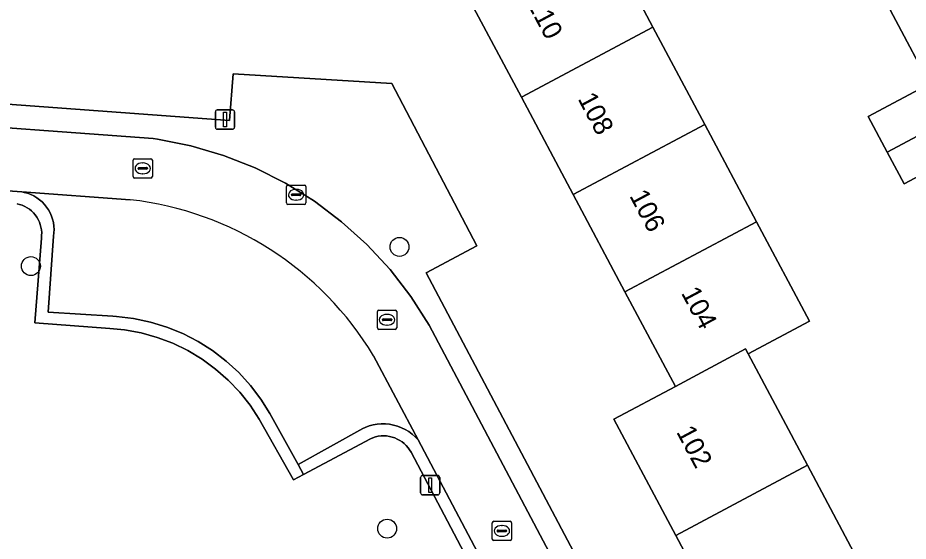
# Model space of a CAD drawing. Extents: x 160304 to 160955, y 383684 to 384161.
# Drawn here: x 160553.59 to 160599.67, y 383895.48 to 383922.54 of the extents above; entities that cross this region are included whole.
import ezdxf

# ---------------------------------------------------------------- set-up
doc = ezdxf.new("R2010")
doc.units = 0
for name, color, linetype in [('IMGEO_Boom', 7, 'Continuous'), ('IMGEO_Erf', 7, 'Continuous'), ('IMGEO_Groenvoorziening', 7, 'Continuous'), ('IMGEO_Kolk', 7, 'Continuous'), ('IMGEO_Lichtmast', 7, 'Continuous'), ('IMGEO_Pand', 7, 'Continuous'), ('IMGEO_Pand_nummerreeks', 7, 'Continuous'), ('IMGEO_Parkeervlak_open', 7, 'Continuous'), ('IMGEO_Rijbaan_lokaal_open', 7, 'Continuous'), ('IMGEO_Rioolput', 7, 'Continuous'), ('IMGEO_Voetpad_open', 7, 'Continuous')]:
    doc.layers.add(name, color=color, linetype=linetype)

msp = doc.modelspace()

# ---------------------------------------------------------------- linework, layer by layer
at = {"layer": 'IMGEO_Boom'}
for centre in [(160573.341, 383910.695), (160554.265, 383909.703), (160572.704, 383896.124)]:
    msp.add_circle(centre, 0.489, dxfattribs=at)
at = {"layer": 'IMGEO_Erf'}
for points in [[(160583.724, 383927.208), (160586.463, 383922.067), (160589.145, 383917.032), (160591.827, 383911.997), (160594.565, 383906.858), (160591.388, 383905.166), (160594.458, 383899.403), (160597.603, 383893.497), (160599.049, 383890.783), (160599.714, 383890.581)], [(160602.636, 383915.645), (160599.458, 383913.953), (160598.584, 383915.595), (160597.607, 383917.431), (160600.784, 383919.123), (160597.283, 383925.699)], [(160519.759, 383920.534), (160564.54, 383917.241), (160564.726, 383919.653), (160572.939, 383919.144), (160577.354, 383910.75), (160574.721, 383909.349), (160588.559, 383883.201), (160593.071, 383885.591), (160590.792, 383889.87), (160587.646, 383895.777), (160584.445, 383901.786), (160587.621, 383903.478), (160585.015, 383908.37), (160582.333, 383913.405), (160579.651, 383918.439), (160576.913, 383923.58)]]:
    msp.add_lwpolyline(points, dxfattribs=at)
at = {"layer": 'IMGEO_Groenvoorziening'}
msp.add_lwpolyline([(160576.867, 383894.551), (160573.94, 383900.071), (160573.867, 383900.195), (160573.783, 383900.312), (160573.689, 383900.42), (160573.585, 383900.52), (160573.473, 383900.611), (160573.354, 383900.691), (160573.227, 383900.759), (160573.095, 383900.817), (160572.959, 383900.862), (160572.819, 383900.895), (160572.677, 383900.916), (160572.533, 383900.923), (160572.389, 383900.918), (160572.247, 383900.9), (160572.106, 383900.869), (160571.969, 383900.826), (160571.848, 383900.776), (160568.374, 383898.921), (160567.854, 383898.643), (160566.087, 383901.784), (160565.611, 383902.506), (160565.073, 383903.183), (160564.476, 383903.809), (160563.826, 383904.379), (160563.127, 383904.888), (160562.386, 383905.333), (160561.607, 383905.711), (160560.799, 383906.017), (160559.966, 383906.249), (160559.115, 383906.407), (160558.358, 383906.482), (160554.474, 383906.761), (160554.807, 383911.153), (160554.821, 383911.293), (160554.822, 383911.434), (160554.81, 383911.575), (160554.786, 383911.714), (160554.749, 383911.85), (160554.701, 383911.983), (160554.641, 383912.11), (160554.569, 383912.232), (160554.488, 383912.347), (160554.396, 383912.454), (160554.295, 383912.553), (160554.185, 383912.642), (160554.068, 383912.721), (160553.945, 383912.789), (160553.816, 383912.846), (160553.682, 383912.891), (160553.545, 383912.924)], dxfattribs=at)
at = {"layer": 'IMGEO_Kolk'}
for p, q in [((160559.553, 383914.332), (160559.553, 383915.184)), ((160559.628, 383915.258), (160560.48, 383915.258)), ((160560.041, 383915.038), (160560.066, 383915.038)), ((160560.554, 383915.184), (160560.554, 383914.332)), ((160559.812, 383914.752), (160559.812, 383914.764)), ((160560.25, 383914.715), (160559.852, 383914.715)), ((160559.855, 383914.801), (160560.253, 383914.801)), ((160560.296, 383914.764), (160560.296, 383914.752)), ((160560.48, 383914.258), (160559.628, 383914.258)), ((160560.064, 383914.478), (160560.039, 383914.478)), ((160572.197, 383906.502), (160572.197, 383907.354)), ((160572.272, 383907.428), (160573.124, 383907.428)), ((160572.685, 383907.208), (160572.71, 383907.208)), ((160573.198, 383907.354), (160573.198, 383906.502)), ((160572.456, 383906.922), (160572.456, 383906.934)), ((160572.894, 383906.885), (160572.496, 383906.885)), ((160572.499, 383906.971), (160572.897, 383906.971)), ((160572.94, 383906.934), (160572.94, 383906.922)), ((160573.124, 383906.428), (160572.272, 383906.428)), ((160572.708, 383906.648), (160572.683, 383906.648)), ((160578.143, 383895.58), (160578.143, 383896.432)), ((160578.218, 383896.506), (160579.07, 383896.506)), ((160578.631, 383896.286), (160578.656, 383896.286)), ((160579.144, 383896.432), (160579.144, 383895.58)), ((160578.402, 383896), (160578.402, 383896.012)), ((160578.84, 383895.963), (160578.442, 383895.963)), ((160578.445, 383896.049), (160578.843, 383896.049)), ((160578.654, 383895.726), (160578.629, 383895.726)), ((160578.886, 383896.012), (160578.886, 383896)), ((160579.07, 383895.506), (160578.218, 383895.506))]:
    msp.add_line(p, q, dxfattribs=at)
for points in [[(160559.553, 383914.332), (160559.553, 383915.184)], [(160559.628, 383915.258), (160560.48, 383915.258)], [(160560.554, 383915.184), (160560.554, 383914.332)], [(160560.48, 383914.258), (160559.628, 383914.258)], [(160572.197, 383906.502), (160572.197, 383907.354)], [(160572.272, 383907.428), (160573.124, 383907.428)], [(160573.198, 383907.354), (160573.198, 383906.502)], [(160573.124, 383906.428), (160572.272, 383906.428)], [(160578.143, 383895.58), (160578.143, 383896.432)], [(160578.218, 383896.506), (160579.07, 383896.506)], [(160579.144, 383896.432), (160579.144, 383895.58)], [(160579.07, 383895.506), (160578.218, 383895.506)]]:
    msp.add_lwpolyline(points, dxfattribs=at)
for centre, radius, start, end in [((160559.63, 383915.182), 0.0765, 91.552, 178.448), ((160559.63, 383915.182), 0.0765, 91.552, 178.448), ((160560.478, 383915.182), 0.0765, 1.552, 88.448), ((160560.478, 383915.182), 0.0765, 1.552, 88.448), ((160559.852, 383914.761), 0.0403, 85.8775, 175.7526), ((160559.849, 383914.751), 0.0366, 178.938, 274.7102), ((160560.253, 383914.758), 0.043, 264.8664, 352.4533), ((160560.257, 383914.763), 0.0386, 1.7309, 96.639), ((160559.63, 383914.334), 0.0765, 181.552, 268.448), ((160559.63, 383914.334), 0.0765, 181.552, 268.448), ((160560.478, 383914.334), 0.0765, 271.552, 358.448), ((160560.478, 383914.334), 0.0765, 271.552, 358.448), ((160572.274, 383907.352), 0.0765, 91.552, 178.448), ((160572.274, 383907.352), 0.0765, 91.552, 178.448), ((160573.122, 383907.352), 0.0765, 1.552, 88.448), ((160573.122, 383907.352), 0.0765, 1.552, 88.448), ((160572.496, 383906.931), 0.0403, 85.8775, 175.7526), ((160572.493, 383906.921), 0.0366, 178.938, 274.7102), ((160572.897, 383906.928), 0.043, 264.8664, 352.4533), ((160572.901, 383906.933), 0.0386, 1.7309, 96.639), ((160572.274, 383906.504), 0.0765, 181.552, 268.448), ((160572.274, 383906.504), 0.0765, 181.552, 268.448), ((160573.122, 383906.504), 0.0765, 271.552, 358.448), ((160573.122, 383906.504), 0.0765, 271.552, 358.448), ((160578.22, 383896.43), 0.0765, 91.552, 178.448), ((160578.22, 383896.43), 0.0765, 91.552, 178.448), ((160579.068, 383896.43), 0.0765, 1.552, 88.448), ((160579.068, 383896.43), 0.0765, 1.552, 88.448), ((160578.442, 383896.009), 0.0403, 85.8775, 175.7526), ((160578.439, 383895.999), 0.0366, 178.938, 274.7102), ((160578.843, 383896.006), 0.043, 264.8664, 352.4533), ((160578.847, 383896.011), 0.0386, 1.7309, 96.639), ((160578.22, 383895.582), 0.0765, 181.552, 268.448), ((160578.22, 383895.582), 0.0765, 181.552, 268.448), ((160579.068, 383895.582), 0.0765, 271.552, 358.448), ((160579.068, 383895.582), 0.0765, 271.552, 358.448)]:
    msp.add_arc(centre, radius, start, end, dxfattribs=at)
for centre, major_axis, ratio, start_param, end_param in [((160560.04, 383914.758), (-0.387, 0.002), 0.722429, 4.712389, 7.853982), ((160560.065, 383914.758), (-0.39, 0.002), 0.717154, 1.570796, 4.712389), ((160572.684, 383906.928), (-0.387, 0.002), 0.722429, 4.712389, 7.853982), ((160572.709, 383906.928), (-0.39, 0.002), 0.717154, 1.570796, 4.712389), ((160578.63, 383896.006), (-0.387, 0.002), 0.722429, 4.712389, 7.853982), ((160578.655, 383896.006), (-0.39, 0.002), 0.717154, 1.570796, 4.712389)]:
    msp.add_ellipse(centre, major_axis=major_axis, ratio=ratio, start_param=start_param, end_param=end_param, dxfattribs=at)
at = {"layer": 'IMGEO_Lichtmast'}
for p, q in [((160563.912, 383917.781), (160564.702, 383917.781)), ((160564.702, 383917.781), (160563.912, 383917.781)), ((160563.812, 383916.881), (160563.812, 383917.681)), ((160563.812, 383917.681), (160563.812, 383916.881)), ((160564.802, 383917.681), (160564.802, 383916.881)), ((160564.802, 383916.881), (160564.802, 383917.681)), ((160564.702, 383916.781), (160563.912, 383916.781)), ((160563.912, 383916.781), (160564.702, 383916.781)), ((160574.536, 383898.873), (160575.326, 383898.873)), ((160575.326, 383898.873), (160574.536, 383898.873)), ((160574.436, 383897.973), (160574.436, 383898.773)), ((160574.436, 383898.773), (160574.436, 383897.973)), ((160575.426, 383898.773), (160575.426, 383897.973)), ((160575.426, 383897.973), (160575.426, 383898.773)), ((160575.326, 383897.873), (160574.536, 383897.873)), ((160574.536, 383897.873), (160575.326, 383897.873))]:
    msp.add_line(p, q, dxfattribs=at)
for points in [[(160564.232, 383917.656), (160564.382, 383917.656), (160564.382, 383916.906), (160564.232, 383916.906), (160564.232, 383917.656)], [(160574.856, 383898.748), (160575.006, 383898.748), (160575.006, 383897.998), (160574.856, 383897.998), (160574.856, 383898.748)]]:
    msp.add_lwpolyline(points, dxfattribs=at)
for centre, start, end in [((160563.912, 383917.681), 90, 180), ((160563.912, 383917.681), 90, 180), ((160564.702, 383917.681), 0, 90), ((160564.702, 383917.681), 360, 90), ((160563.912, 383916.881), 180, 270), ((160563.912, 383916.881), 180, 270), ((160564.702, 383916.881), 270, 0), ((160564.702, 383916.881), 270, 0), ((160574.536, 383898.773), 90, 180), ((160574.536, 383898.773), 90, 180), ((160575.326, 383898.773), 0, 90), ((160575.326, 383898.773), 360, 90), ((160574.536, 383897.973), 180, 270), ((160574.536, 383897.973), 180, 270), ((160575.326, 383897.973), 270, 0), ((160575.326, 383897.973), 270, 0)]:
    msp.add_arc(centre, 0.1, start, end, dxfattribs=at)
at = {"layer": 'IMGEO_Pand'}
for points in [[(160579.651, 383918.439), (160586.463, 383922.067), (160583.724, 383927.208), (160576.913, 383923.58)], [(160582.333, 383913.405), (160589.145, 383917.032), (160586.463, 383922.067), (160579.651, 383918.439)], [(160598.584, 383915.595), (160601.762, 383917.287), (160600.784, 383919.123), (160597.607, 383917.431)], [(160598.584, 383915.595), (160599.458, 383913.953), (160602.636, 383915.645), (160601.762, 383917.287)], [(160591.827, 383911.997), (160589.145, 383917.032), (160582.333, 383913.405), (160585.015, 383908.37)], [(160591.827, 383911.997), (160585.015, 383908.37), (160587.621, 383903.478), (160591.255, 383905.416), (160591.388, 383905.166), (160594.565, 383906.858)], [(160587.646, 383895.777), (160594.458, 383899.403), (160591.388, 383905.166), (160591.255, 383905.416), (160587.621, 383903.478), (160584.445, 383901.786)], [(160587.646, 383895.777), (160590.792, 383889.87), (160597.603, 383893.497), (160594.458, 383899.403)]]:
    msp.add_lwpolyline(points, close=True, dxfattribs=at)
at = {"layer": 'IMGEO_Parkeervlak_open'}
msp.add_lwpolyline([(160559.41, 383913.131), (160553.8, 383913.536), (160553.919, 383913.513), (160554.089, 383913.467), (160554.255, 383913.405), (160554.415, 383913.329), (160554.567, 383913.239), (160554.711, 383913.135), (160554.845, 383913.02), (160554.967, 383912.892), (160555.079, 383912.755), (160555.177, 383912.608), (160555.262, 383912.452), (160555.332, 383912.29), (160555.388, 383912.122), (160555.429, 383911.95), (160555.454, 383911.775), (160555.463, 383911.598), (160555.456, 383911.421), (160555.434, 383911.246), (160555.163, 383907.324), (160558.502, 383907.106), (160558.694, 383907.094), (160559.577, 383906.991), (160560.448, 383906.809), (160561.299, 383906.55), (160562.123, 383906.216), (160562.914, 383905.809), (160563.666, 383905.334), (160564.372, 383904.793), (160565.027, 383904.192), (160565.626, 383903.534), (160566.164, 383902.826), (160566.636, 383902.072), (160568.094, 383899.444), (160571.447, 383901.307), (160571.566, 383901.361), (160571.768, 383901.434), (160571.975, 383901.489), (160572.187, 383901.526), (160572.401, 383901.543), (160572.615, 383901.542), (160572.829, 383901.521), (160573.04, 383901.481), (160573.246, 383901.422), (160573.447, 383901.346), (160573.639, 383901.251), (160573.823, 383901.14), (160573.996, 383901.013), (160574.157, 383900.871), (160574.304, 383900.715), (160572.002, 383905.066)], dxfattribs=at)
msp.add_arc((160557.519, 383896.316), 16.922, 31.1394, 83.5826, dxfattribs=at)
at = {"layer": 'IMGEO_Rijbaan_lokaal_open'}
for points in [[(160590.253, 383880.91), (160590.026, 383881.001), (160589.501, 383881.251), (160588.999, 383881.548), (160588.526, 383881.888), (160588.086, 383882.269), (160587.681, 383882.688), (160587.654, 383882.722), (160587.315, 383883.141), (160574.877, 383906.644), (160573.929, 383908.129), (160572.852, 383909.524), (160571.655, 383910.817), (160570.347, 383911.997), (160568.939, 383913.056), (160567.441, 383913.986), (160565.867, 383914.777), (160564.229, 383915.425), (160562.539, 383915.924), (160560.811, 383916.27), (160560.601, 383916.301), (160547.853, 383917.226)], [(160547.655, 383913.98), (160553.8, 383913.536), (160559.41, 383913.131)], [(160572.002, 383905.066), (160574.304, 383900.715), (160577.703, 383894.291), (160586.778, 383877.294), (160587.812, 383875.31)]]:
    msp.add_lwpolyline(points, dxfattribs=at)
msp.add_arc((160557.519, 383896.316), 16.922, 31.1394, 83.5826, dxfattribs=at)
at = {"layer": 'IMGEO_Rioolput'}
for p, q in [((160567.493, 383912.966), (160567.493, 383913.818)), ((160567.568, 383913.892), (160568.42, 383913.892)), ((160567.981, 383913.672), (160568.006, 383913.672)), ((160568.494, 383913.818), (160568.494, 383912.966)), ((160567.752, 383913.386), (160567.752, 383913.398)), ((160568.19, 383913.349), (160567.792, 383913.349)), ((160567.795, 383913.435), (160568.193, 383913.435)), ((160568.236, 383913.398), (160568.236, 383913.386)), ((160568.42, 383912.892), (160567.568, 383912.892)), ((160568.004, 383913.112), (160567.979, 383913.112))]:
    msp.add_line(p, q, dxfattribs=at)
for points in [[(160567.493, 383912.966), (160567.493, 383913.818)], [(160567.568, 383913.892), (160568.42, 383913.892)], [(160568.494, 383913.818), (160568.494, 383912.966)], [(160568.42, 383912.892), (160567.568, 383912.892)]]:
    msp.add_lwpolyline(points, dxfattribs=at)
for centre, radius, start, end in [((160567.57, 383913.816), 0.0765, 91.552, 178.448), ((160567.57, 383913.816), 0.0765, 91.552, 178.448), ((160568.418, 383913.816), 0.0765, 1.552, 88.448), ((160568.418, 383913.816), 0.0765, 1.552, 88.448), ((160567.792, 383913.395), 0.0403, 85.8775, 175.7526), ((160567.789, 383913.385), 0.0366, 178.938, 274.7102), ((160568.193, 383913.392), 0.043, 264.8664, 352.4533), ((160568.197, 383913.397), 0.0386, 1.7309, 96.639), ((160567.57, 383912.968), 0.0765, 181.552, 268.448), ((160567.57, 383912.968), 0.0765, 181.552, 268.448), ((160568.418, 383912.968), 0.0765, 271.552, 358.448), ((160568.418, 383912.968), 0.0765, 271.552, 358.448)]:
    msp.add_arc(centre, radius, start, end, dxfattribs=at)
for centre, major_axis, ratio, start_param, end_param in [((160567.98, 383913.392), (-0.387, 0.002), 0.722429, 4.712389, 7.853982), ((160568.005, 383913.392), (-0.39, 0.002), 0.717154, 1.570796, 4.712389)]:
    msp.add_ellipse(centre, major_axis=major_axis, ratio=ratio, start_param=start_param, end_param=end_param, dxfattribs=at)
at = {"layer": 'IMGEO_Voetpad_open'}
for points in [[(160597.283, 383925.699), (160600.784, 383919.123)], [(160514.136, 383919.672), (160545.126, 383917.424), (160547.853, 383917.226), (160560.601, 383916.301), (160560.811, 383916.27), (160562.539, 383915.924), (160564.229, 383915.425), (160565.867, 383914.777), (160567.441, 383913.986), (160568.939, 383913.056), (160570.347, 383911.997), (160571.655, 383910.817), (160572.852, 383909.524), (160573.929, 383908.129), (160574.877, 383906.644), (160587.315, 383883.141), (160587.654, 383882.722), (160588.559, 383883.201), (160574.721, 383909.349), (160577.354, 383910.75), (160572.939, 383919.144), (160564.726, 383919.653), (160564.54, 383917.241), (160519.759, 383920.534)], [(160553.545, 383912.924), (160553.682, 383912.891), (160553.816, 383912.846), (160553.945, 383912.789), (160554.068, 383912.721), (160554.185, 383912.642), (160554.295, 383912.553), (160554.396, 383912.454), (160554.488, 383912.347), (160554.569, 383912.232), (160554.641, 383912.11), (160554.701, 383911.983), (160554.749, 383911.85), (160554.786, 383911.714), (160554.81, 383911.575), (160554.822, 383911.434), (160554.821, 383911.293), (160554.807, 383911.153), (160554.474, 383906.761), (160558.358, 383906.482), (160559.115, 383906.407), (160559.966, 383906.249), (160560.799, 383906.017), (160561.607, 383905.711), (160562.386, 383905.333), (160563.127, 383904.888), (160563.826, 383904.379), (160564.476, 383903.809), (160565.073, 383903.183), (160565.611, 383902.506), (160566.087, 383901.784), (160567.854, 383898.643), (160568.374, 383898.921), (160568.094, 383899.444), (160566.636, 383902.072), (160566.164, 383902.826), (160565.626, 383903.534), (160565.027, 383904.192), (160564.372, 383904.793), (160563.666, 383905.334), (160562.914, 383905.809), (160562.123, 383906.216), (160561.299, 383906.55), (160560.448, 383906.809), (160559.577, 383906.991), (160558.694, 383907.094), (160558.502, 383907.106), (160555.163, 383907.324), (160555.434, 383911.246), (160555.456, 383911.421), (160555.463, 383911.598), (160555.454, 383911.775), (160555.429, 383911.95), (160555.388, 383912.122), (160555.332, 383912.29), (160555.262, 383912.452), (160555.177, 383912.608), (160555.079, 383912.755), (160554.967, 383912.892), (160554.845, 383913.02), (160554.711, 383913.135), (160554.567, 383913.239), (160554.415, 383913.329), (160554.255, 383913.405), (160554.089, 383913.467), (160553.919, 383913.513), (160553.8, 383913.536), (160547.655, 383913.98)], [(160577.703, 383894.291), (160574.304, 383900.715), (160574.157, 383900.871), (160573.996, 383901.013), (160573.823, 383901.14), (160573.639, 383901.251), (160573.447, 383901.346), (160573.246, 383901.422), (160573.04, 383901.481), (160572.829, 383901.521), (160572.615, 383901.542), (160572.401, 383901.543), (160572.187, 383901.526), (160571.975, 383901.489), (160571.768, 383901.434), (160571.566, 383901.361), (160571.447, 383901.307), (160568.094, 383899.444), (160568.374, 383898.921), (160571.848, 383900.776)], [(160571.848, 383900.776), (160571.969, 383900.826), (160572.106, 383900.869), (160572.247, 383900.9), (160572.389, 383900.918), (160572.533, 383900.923), (160572.677, 383900.916), (160572.819, 383900.895), (160572.959, 383900.862), (160573.095, 383900.817), (160573.227, 383900.759), (160573.354, 383900.691), (160573.473, 383900.611), (160573.585, 383900.52), (160573.689, 383900.42), (160573.783, 383900.312), (160573.867, 383900.195), (160573.94, 383900.071), (160576.867, 383894.551)]]:
    msp.add_lwpolyline(points, dxfattribs=at)

# ---------------------------------------------------------------- texts
at = {"layer": 'IMGEO_Pand_nummerreeks'}
for s, rotation, p in [('110', 298.0435, (160579.915, 383923.306)), ('108', 298.0435, (160582.55, 383918.359)), ('106', 298.0435, (160585.225, 383913.338)), ('104', 298.0435, (160587.902, 383908.312)), ('102', 298.0418, (160587.65, 383901.13))]:
    msp.add_text(s, height=1, rotation=rotation, dxfattribs=at).set_placement(p)

doc.saveas('drawing.dxf')
